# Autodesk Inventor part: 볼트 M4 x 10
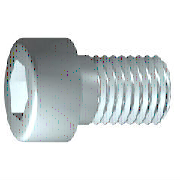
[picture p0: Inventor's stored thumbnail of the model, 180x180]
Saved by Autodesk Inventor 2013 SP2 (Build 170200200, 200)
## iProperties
IsCustomPart: 0
Created: 2012-02
Part Number: 볼트 M4 x 10
Material: 스테인리스강
Description: 6각 소켓 머리 캡 나사
Document SubType Name: Modeling
Standard: ISO 4762
Designer: mduedu
Standard Revision: Fourth edition 2004-03-01
Standards Organization: ISO
Language: ko-KR
Size Designation: M4 x 10
Categories: <MemberInstance><Categories><Category DisplayName="조임쇠" InternalName="e4da775c-781d-43d5-af7c-5136215cf5a6" Mnemonic="FSTN"><Category DisplayName="볼트" InternalN
Density: 8.08 g/cm^3
Author: mduedu
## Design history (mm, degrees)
sketch "스케치1"
  geometry: L1 (-1, 0)-(10, 0); L2 (10, 0)-(10, 2); L3 (10, 2)-(1.75, 2); L4 (1.75, 2)-(1.32, 2); L5 (1.32, 2)-(0, 2); L6 (0, 2)-(0, 3.5); L7 (0, 3.5)-(-4, 3.5); L8 (-4, 3.5)-(-4, 1.732); L9 (-4, 1.732)-(-2, 1.732); L10 (-2, 1.732)-(-1, 0); L11 (-6.8, 0)-(12.8, 0) reference; L12 (0, -0.7)-(0, 4.2) reference; L13 (1.75, 2)-(0, 2)
  constraints: 22 end point, 6 parallel, 2 collinear, 2 perpendicular, 1 horizontal, 1 point on line
  dimensions: "d1" = 8.25 distance from line of L3.end L2 (= GEL); "d2" = 0.42952 distance of L4.end L3.end (computed from GAL); "d3" = 4 distance between parallel lines of L8 L6 (= KOH); "d4" = 2 distance of L8.end L9.end (= INTI); "d5" = 60 deg angle of L10 L1; "d6" = 4 diameter of L3 L1 (= GD); "d7" = 4 diameter of L5 L1 (= BDM); "d8" = 3.4641 diameter of L9 L1 (= 1.1547 x SW); "d9" = 7 diameter of L7 L1 (= KOD); "d26" = 10 distance between parallel lines of L12 L2 (= NLG)
revolve "본체" sketch "스케치1" stored, may be unused: angle "d10" = 90 deg
sketch "스케치2"
  geometry: L1 (0, -4.9)-(0, 4.9) reference; L2 (-4.9, 0)-(4.9, 0) reference; L3 (1.732, 0)-(0.866, -1.5); L4 (0.866, -1.5)-(-0.866, -1.5); L5 (-0.866, -1.5)-(-1.732, 0); L6 (-1.732, 0)-(-0.866, 1.5); L7 (-0.866, 1.5)-(0.866, 1.5); L8 (0.866, 1.5)-(1.732, 0); 2 further points
  constraints: 12 end point, 1 coincident, 1 horizontal alignment, 1 point on line, 12 other
extrude "슬롯" join sketch "스케치2" stored distance "d11" = 10; taper "d12" = 0 deg
workplane "Work Plane1"
fillet "Fillet2" dims "d30" = 0.1 (= R)
body "Solid1"
fillet "모깎기1" dims "d17" = 0.4 (= RR)
feature "스레드" dims "d13" = 8.25 (= GEL), "d14" = 0
chamfer "모따기1" distance "d15" = 0.42941 (= -0.5 x SPD + 0.5 x GD); stored, may be unused: second distance "d16" = 0.42941 (= GUL), angle "d27" = 45 deg
other parameters: "GD" = 4 [user parameter; used in 2 equation terms], "NLG" = 10 [user parameter; used in 1 equation term], "GEL" = 8.25 [user parameter; used in 2 equation terms], "KOD" = 7 [user parameter; used in 1 equation term], "KOH" = 4 [user parameter; used in 1 equation term], "INTI" = 2 [user parameter; used in 1 equation term], "GAL" = 0.42941 (= 0.61345 x PTC) [user parameter; used in 1 equation term], "GUL" = 0.42941 (= 0.61345 x PTC) [user parameter; used in 1 equation term], "BDM" = 4 (= NND) [user parameter; used in 1 equation term], "SW" = 3 [user parameter; used in 2 equation terms], "RR" = 0.4 [user parameter; used in 1 equation term], "SPD" = 3.14117 (= NND - 1.2269 x PTC) [user parameter; used in 1 equation term], "d19" = 0, "d28" = 0, "d29" = 0, "R" = 0.1 [user parameter; used in 1 equation term], "TOA" = 30 deg [user parameter], "GD1" = 3.14117 (= THREADDIA - 1.2269 x PTC) [user parameter], "THREADDIA" = 4 [user parameter; used in 1 equation term], "FAWI" = 45 deg [user parameter], "TPU" = 14.28571 (computed from PTC) [user parameter], "PTC" = 0.7 [user parameter; used in 5 equation terms], "NND" = 4 [user parameter; used in 2 equation terms], "E0" = 3.465 (= 1.155 x SW) [user parameter]
